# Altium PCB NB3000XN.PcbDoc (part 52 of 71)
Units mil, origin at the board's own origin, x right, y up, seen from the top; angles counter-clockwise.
Board outline 9527.56 x 6929.77 mil, 6 copper layers (Top Layer, GND+SHIELD, MidLayer1, MidLayer2, P2 - 3V3+5V0, Bottom Layer), stack 62.375 mil thick; 832 components, 1027 nets, 4655 pads, 4981 vias.
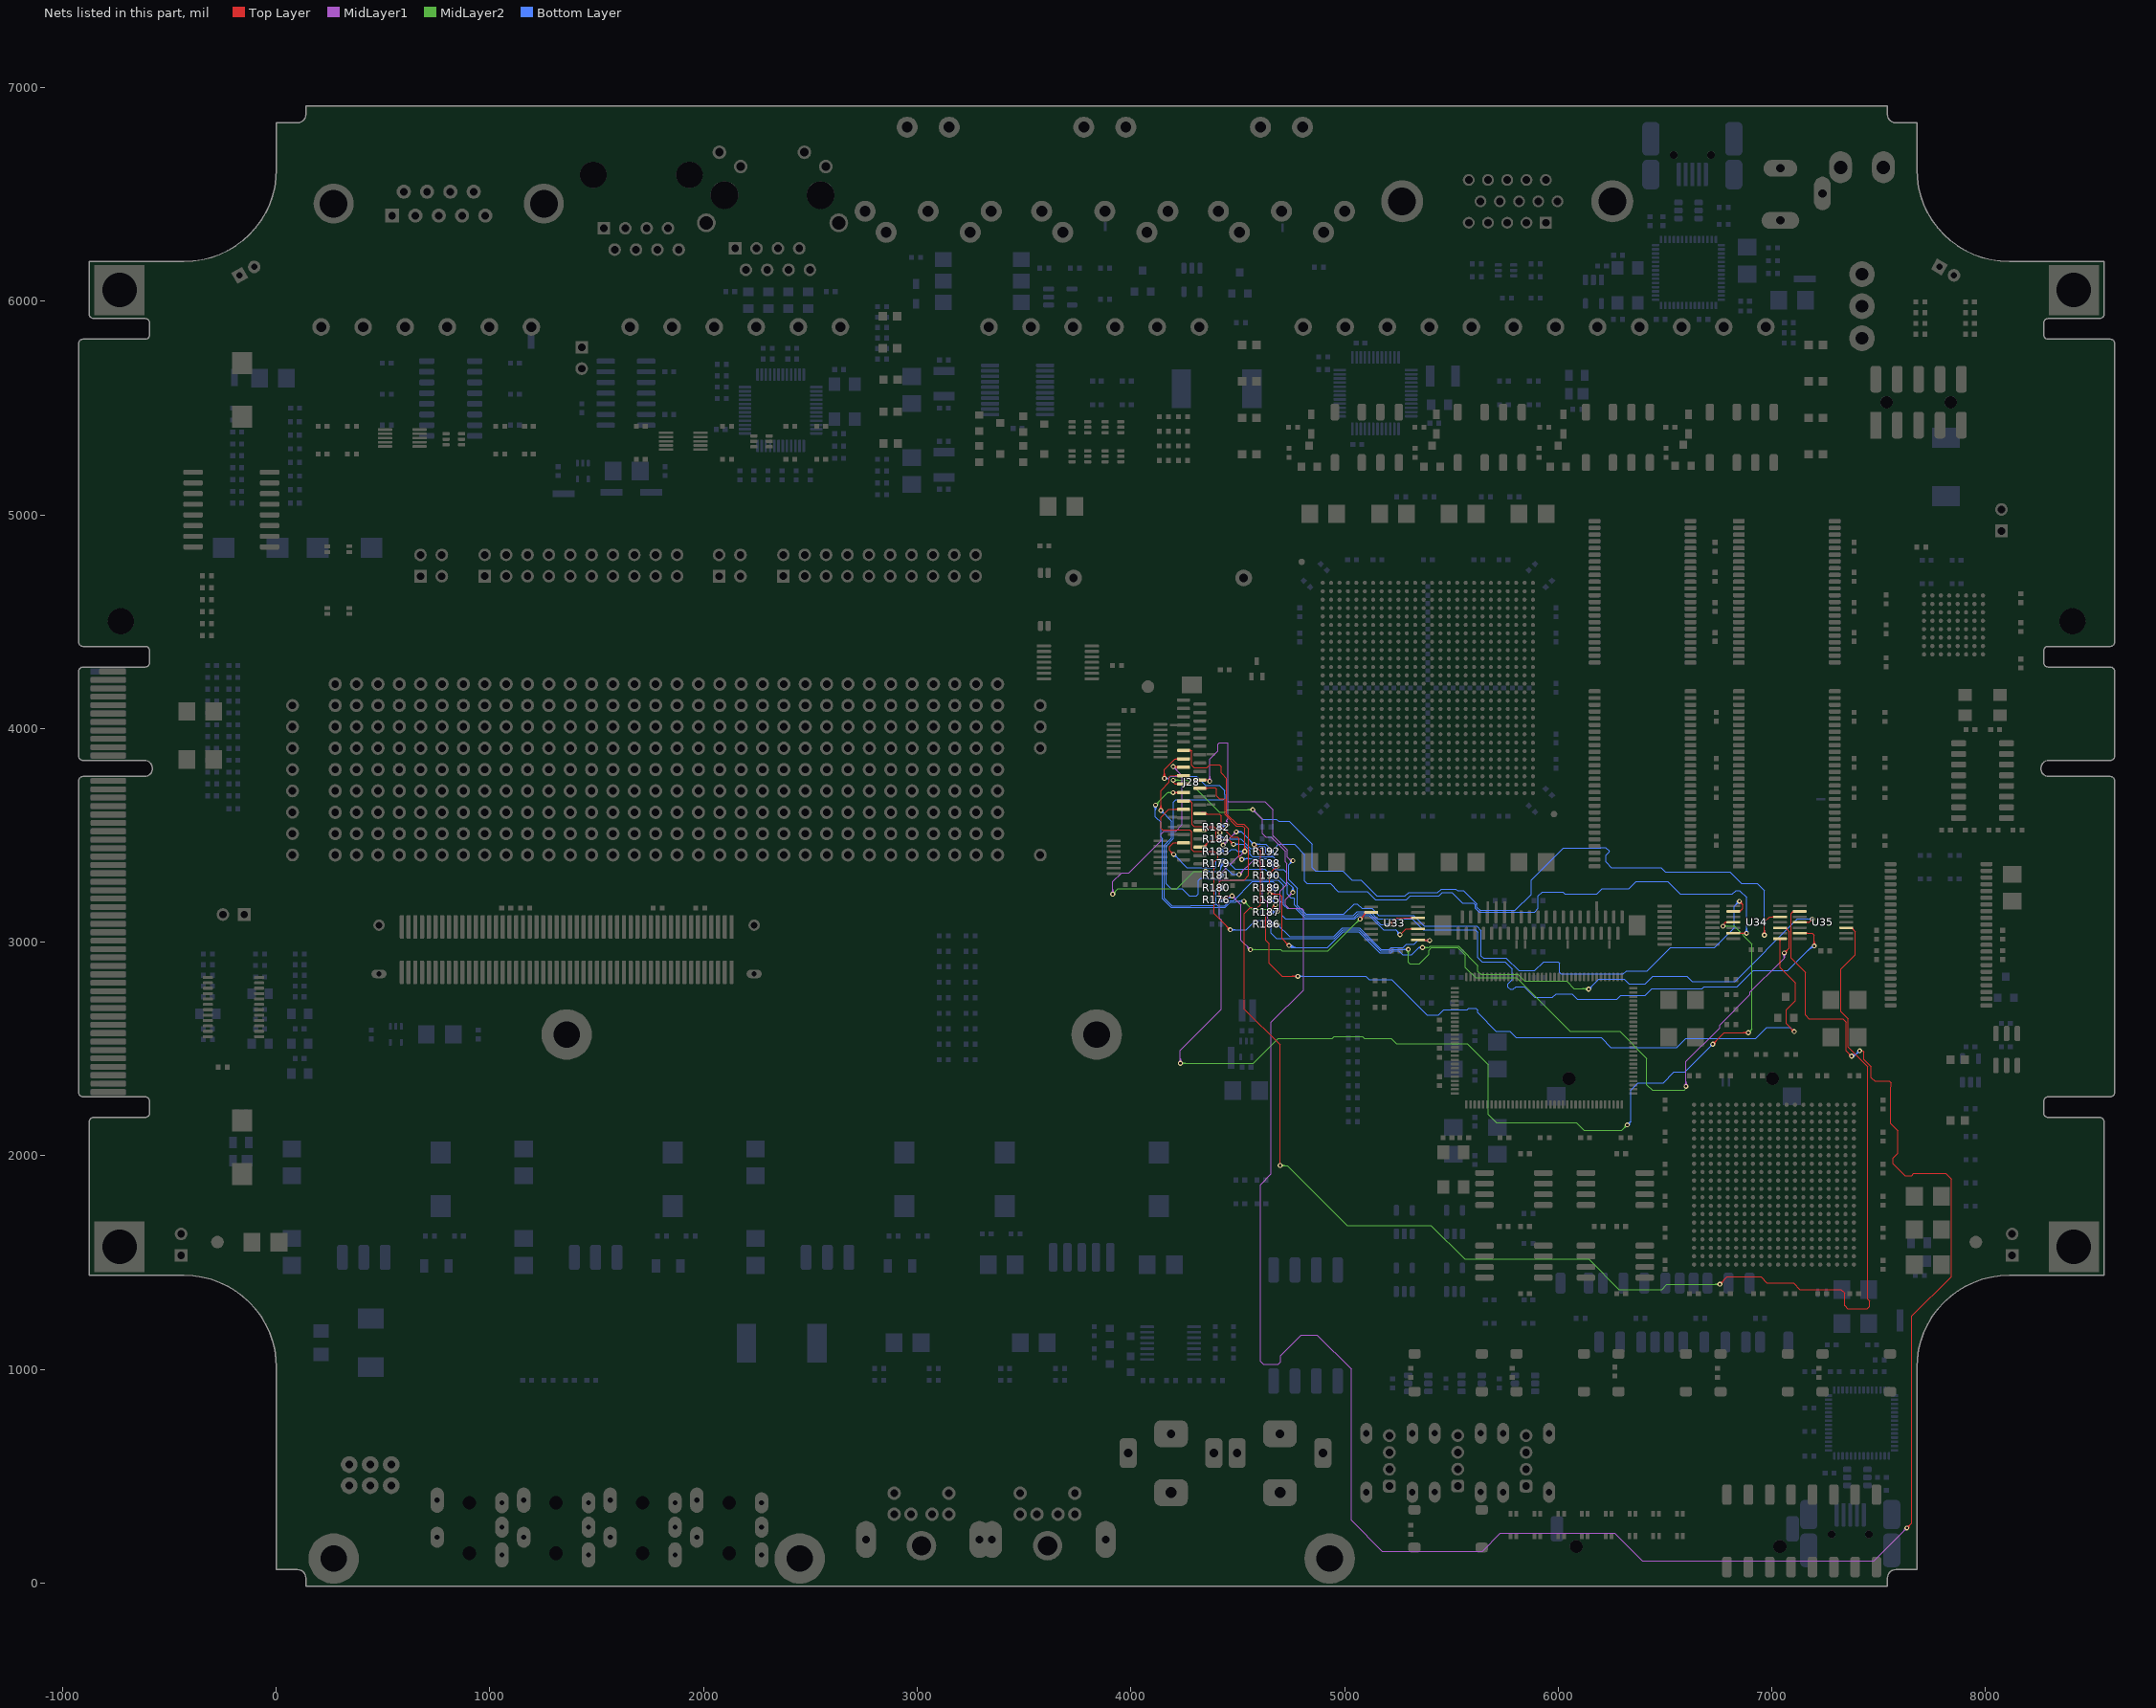
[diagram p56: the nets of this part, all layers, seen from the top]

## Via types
v1: diameter 23, hole 11.81, Top Layer to Bottom Layer, 3672 vias
v2: diameter 26, hole 11.81, Top Layer to Bottom Layer, 461 vias
v3: diameter 19, hole 11.81, Top Layer to Bottom Layer, tented both sides, 396 vias
v4: diameter 23.62, hole 11.81, Top Layer to Bottom Layer, 288 vias
v5: diameter 20, hole 11.81, Top Layer to Bottom Layer, 91 vias
v6: diameter 23, hole 11.81, Top Layer to Bottom Layer, tented both sides, 50 vias
v7: diameter 31, hole 11.81, Top Layer to Bottom Layer, 15 vias
v8: diameter 27.56, hole 11.81, Top Layer to Bottom Layer, tented both sides, 4 vias
v9: diameter 29, hole 11.81, Top Layer to Bottom Layer, 3 vias
v10: diameter 21, hole 11.81, Top Layer to Bottom Layer, 1 vias

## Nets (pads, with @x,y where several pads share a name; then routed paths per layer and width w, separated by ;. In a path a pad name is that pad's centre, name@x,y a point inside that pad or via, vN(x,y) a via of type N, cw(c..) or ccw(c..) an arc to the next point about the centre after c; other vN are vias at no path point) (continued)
LEDS#.LED2.RED: J28.13 R176.2 U33.2 | length 2543.8
  Top Layer w4: J28.13@4246.61,3897.64 4281.86,3897.64 ; J28.13@4273.12,3893.73 cw(c4281.86,3885.93) 4281.86,3897.64 ; J28.13@4273.12,3901.55 ccw(c4281.86,3909.34) 4281.86,3897.64 ; 4451.86,3210 4458.56,3216.71 ; v1(4473.52,3216.71) 4458.56,3216.71 ; v1(5073.52,3108.37) 5098.52,3133.37 ; v1@5073.52,3113.87 ccw(c5073.52,3127.15) 5082.91,3117.76 ccw(c5092.3,3108.37) v1@5079.02,3108.37 ; v1@5073.52,3117.87 ccw(c5073.52,3140.81) 5089.74,3124.59 ccw(c5105.96,3108.37) v1@5083.02,3108.37 ; 5087.42,3122.27 ccw(c5070.28,3139.41) U33.2@5094.52,3139.41 ; 5094.25,3129.1 ccw(c5083.94,3139.41) U33.2@5098.52,3139.41 ; U33.2@5096.97,3135.72 cw(c5095.97,3133.38) 5098.52,3133.38 ; U33.2@5100.08,3135.73 ccw(c5101.08,3133.38) 5098.52,3133.38 ; U33.2@5125,3139.41 U33.2@5098.52,3139.41 ; 4281.86,3897.64 4283.52,3895.97 4283.52,3828.71 4295.52,3816.71 4356.71,3816.71 4370.58,3830.58 4415,3830.58 4423.52,3822.06 4423.52,3791.71 4448.52,3766.71 4448.52,3606.71 4448.52,3601 4496.82,3552.71 4529.19,3552.71 4551.19,3530.71 4551.19,3312.9 4530,3291.71 4425.19,3291.71 4415.19,3281.71 4415.19,3216.71 4423.52,3208.37 4450.23,3208.37 4458.56,3216.71 ; 5098.52,3133.37 U33.2@5098.52,3139.41
  MidLayer1 w4: v1@4473.52,3207.21 cw(c4473.52,3184.27) 4489.74,3200.49 cw(c4505.96,3216.71) v1@4483.02,3216.71 ; v1@4473.52,3211.21 cw(c4473.52,3197.93) 4482.91,3207.32 cw(c4492.3,3216.71) v1@4479.02,3216.71 ; v1(4473.52,3216.71) 4515.19,3175.04 4515.19,3009.37 v1(4559.52,2965.04) ; v1@4550.02,2965.04 ccw(c4527.09,2965.04) 4543.31,2981.26 ccw(c4559.52,2997.48) v1@4559.52,2974.54 ; v1@4554.02,2965.04 ccw(c4540.75,2965.04) 4550.14,2974.43 ccw(c4559.52,2983.82) v1@4559.52,2970.54
  MidLayer2 w4: v1(4559.52,2965.04) 4700.19,2965.04 4706.86,2958.37 4923.52,2958.37 v1(5073.52,3108.37) ; v1@4563.41,2961.15 cw(c4572.8,2951.76) 4572.8,2965.04 cw(c4572.8,2978.32) v1@4563.41,2968.93 ; v1@4566.24,2958.32 cw(c4582.46,2942.11) 4582.46,2965.04 cw(c4582.46,2987.98) v1@4566.24,2971.76 ; v1@5064.02,3108.37 cw(c5041.09,3108.37) 5057.31,3092.16 cw(c5073.52,3075.94) v1@5073.52,3098.87 ; v1@5068.02,3108.37 cw(c5054.75,3108.37) 5064.14,3098.99 cw(c5073.52,3089.6) v1@5073.52,3102.87
  Bottom Layer w4: R176.2@4421.18,3198.75 4440.86,3198.75 ; R176.2@4428.39,3192.85 cw(c4440.86,3182.64) 4440.86,3198.75 ; R176.2@4428.39,3204.65 ccw(c4440.86,3214.86) 4440.86,3198.75 ; 4455.42,3208.37 ccw(c4455.42,3221.63) v1@4468.22,3218.15 ; 4460.66,3208.37 ccw(c4460.66,3220.21) v1@4472.08,3217.1 ; v1@4464.36,3219.2 cw(c4450.19,3223.06) 4450.19,3208.37 ; v1(4473.52,3216.71) 4465.19,3208.37 4450.19,3208.37 ; 4440.86,3198.75 4440.86,3199.04 4450.19,3208.37
LEDS#.LED3.BLUE: J28.19 R180.2 U33.10 | length 2457.1
  Top Layer w4: v1@4133.47,3623.43 ccw(c4117.26,3639.64) 4140.19,3639.64 ccw(c4163.13,3639.64) v1@4146.91,3623.43 ; v1@4136.3,3620.6 ccw(c4126.91,3629.99) 4140.19,3629.99 ccw(c4153.47,3629.99) v1@4144.08,3620.6 ; v1(4140.19,3616.71) 4140.19,3710.19 4180,3750 4180,3775 4185,3780 4246.14,3780 J28.19@4246.61,3779.53 ; 4209.17,3780 cw(c4209.17,3764.21) J28.19@4220.33,3775.37 ; 4211.45,3780 ccw(c4211.45,3792.57) J28.19@4220.33,3783.68 ; v1(5260,3035) 5260.15,3035 5287.79,3062.64 U33.10@5343.5,3062.64 ; U33.10@5314.2,3059.81 ccw(c5307.37,3052.98) 5307.37,3062.64 ccw(c5307.37,3072.29) U33.10@5314.2,3065.47
  Bottom Layer w4: v1@4140.19,3607.21 cw(c4140.19,3584.27) 4156.41,3600.49 cw(c4172.63,3616.71) v1@4149.69,3616.71 ; v1@4140.19,3611.21 cw(c4140.19,3597.93) 4149.58,3607.32 cw(c4158.97,3616.71) v1@4145.69,3616.71 ; v1(4140.19,3616.71) 4190.19,3566.71 4190.19,3487.37 4156.86,3454.04 4156.86,3235 4156.86,3206 4191.82,3171.04 4281.04,3171.04 4281.37,3171.37 4390.19,3171.37 4398.52,3179.71 ; R180.2@4412.74,3251.67 ccw(c4406.52,3248.76) 4406.52,3255.62 ; R180.2@4412.74,3259.58 cw(c4406.52,3262.49) 4406.52,3255.62 ; R180.2@4421.18,3255.62 4406.52,3255.62 ; 5241.26,3057.3 cw(c5218.96,3035) v1@5250.5,3035 ; 5248.09,3050.47 cw(c5232.62,3035) v1@5254.5,3035 ; 5249.87,3048.7 ccw(c5260,3058.83) v1@5260,3044.5 ; v1(5260,3035) 5260.15,3035.15 5260.15,3038.42 5240.19,3058.37 5182.86,3058.37 5115.19,3126.04 5066.19,3126.04 5048.52,3108.37 4723.52,3108.37 4706.86,3125.04 4706.86,3183.37 4673.52,3216.71 4673.52,3275.04 4665.19,3283.37 4569.86,3283.37 4481.86,3195.37 4462.9,3195.37 4438.56,3171.04 4407.19,3171.04 4403.19,3175.04 4398.52,3179.71 ; 4398.52,3179.71 4398.52,3247.62 4406.52,3255.62
LEDS#.LED3.GREEN: J28.15 R181.2 U33.12 | length 2846.8
  Top Layer w4: v1@4150.14,3773.43 ccw(c4133.92,3789.64) 4156.86,3789.64 ccw(c4179.79,3789.64) v1@4163.57,3773.43 ; v1@4152.97,3770.6 ccw(c4143.58,3779.99) 4156.86,3779.99 ccw(c4170.14,3779.99) v1@4160.75,3770.6 ; v1(4156.86,3766.71) 4156.86,3808.37 4206.75,3858.27 J28.15@4246.61,3858.27 J28.15@4248.52,3858.27 ; J28.15@4220.33,3854.11 ccw(c4210.31,3844.09) 4210.31,3858.27 ccw(c4210.31,3872.45) J28.15@4220.33,3862.42 ; v1(5215.19,3083.37) 5245.64,3113.82 U33.12@5343.5,3113.82 ; v1@5215.19,3088.87 ccw(c5215.19,3102.15) 5224.58,3092.76 ccw(c5233.97,3083.37) v1@5220.69,3083.37 ; v1@5215.19,3092.87 ccw(c5215.19,3115.81) 5231.41,3099.59 ccw(c5247.63,3083.37) v1@5224.69,3083.37 ; U33.12@5314.2,3110.99 ccw(c5307.37,3104.16) 5307.37,3113.82 ccw(c5307.37,3123.48) U33.12@5314.2,3116.65
  Bottom Layer w4: v1(4156.86,3766.71) 4175.67,3766.71 ; v1@4164.5,3761.07 cw(c4175.67,3752.84) 4175.67,3766.71 ; v1@4164.5,3772.35 ccw(c4175.67,3780.58) 4175.67,3766.71 ; R181.2@4421.18,3312.5 4421.18,3299.71 4415.85,3294.37 ; 4440,3692.63 4440,3708.69 4415.31,3733.37 4348.52,3733.37 4305.86,3776.04 4185,3776.04 4175.67,3766.71 ; 4440.19,3692.63 4440.19,3674.04 4432.86,3666.71 4211.71,3666.71 4200,3655 4200,3485.87 4164.86,3450.73 4164.86,3272.39 4187.21,3250.04 4240.19,3250.04 4273.52,3216.71 4306.86,3216.71 4315.19,3225.04 4315.19,3287.71 4327.52,3300.04 4357.86,3300.04 4363.52,3294.37 4415.85,3294.37 ; v1@5208.47,3076.66 ccw(c5192.26,3060.44) 5192.26,3083.37 ccw(c5192.26,3106.31) v1@5208.47,3090.09 ; v1@5211.3,3079.49 ccw(c5201.91,3070.1) 5201.91,3083.37 ccw(c5201.91,3096.65) v1@5211.3,3087.26 ; v1(5215.19,3083.37) 5169.17,3083.37 5118.5,3134.04 5062.88,3134.04 5045.21,3116.37 4812.54,3116.37 4770.54,3158.37 4731.86,3158.37 4715.19,3175.04 4715.19,3266.71 4690.19,3291.71 4418.51,3291.71 4415.85,3294.37
LEDS#.LED3.RED: J28.17 R179.2 U33.8 | length 3712.4
  Top Layer w4: v1(4198.19,3822.04) 4201.86,3818.37 v1@4205.19,3818.37 ; v1@4199.25,3823.1 ccw(c4209.4,3833.25) 4209.4,3818.9 ; v1@4202.08,3825.93 ccw(c4219.06,3842.91) J28.17@4219.06,3818.9 ; v1@4204.91,3815.32 cw(c4213.54,3806.69) 4213.54,3818.9 ; v1@4204.91,3828.76 ccw(c4228.71,3852.56) J28.17@4228.71,3818.9 ; v1@4205.71,3818.9 J28.17@4246.61,3818.9 ; J28.17@4220.33,3814.74 ccw(c4210.31,3804.72) 4210.31,3818.9 ccw(c4210.31,3833.08) J28.17@4220.33,3823.05 ; U33.8@5343.5,3011.46 5340.19,3011.46 5340.19,3008.37 5343.5,3008.37 v1(5398.52,3008.37) ; U33.8@5369.98,3011.46 ccw(c5377.43,3018.9) 5377.43,3008.37 ; U33.8@5372.81,3014.29 ccw(c5387.08,3028.56) v1@5387.08,3008.37 ; v1@5391.81,3001.66 ccw(c5375.59,2985.44) 5375.59,3008.37 ccw(c5375.59,3031.31) v1@5391.81,3015.09 ; v1@5394.64,3004.49 ccw(c5385.25,2995.1) 5385.25,3008.37 ccw(c5385.25,3021.65) v1@5394.64,3012.26
  MidLayer1 w4: v1@3908.47,3231.76 ccw(c3892.26,3247.98) 3915.19,3247.98 ccw(c3938.13,3247.98) v1@3921.91,3231.76 ; v1@3911.3,3228.93 ccw(c3901.91,3238.32) 3915.19,3238.32 ccw(c3928.47,3238.32) v1@3919.08,3228.93 ; v1(3915.19,3225.04) 3915.19,3283.37 3956.86,3325.04 3991.19,3325.04 4140.19,3474.04 4140.19,3505.04 4155.15,3520 4210.15,3520 4240.19,3550.04 4240.19,3780.04 v1(4198.19,3822.04) ; v1@4198.19,3812.54 cw(c4198.19,3789.61) 4214.41,3805.82 cw(c4230.63,3822.04) v1@4207.69,3822.04 ; v1@4198.19,3816.54 cw(c4198.19,3803.26) 4207.58,3812.65 cw(c4216.97,3822.04) v1@4203.69,3822.04 ; v1(4506.86,3316.71) 4573.52,3383.37 4598.52,3383.37 4615.19,3366.71 4615.19,3208.37 4640.19,3183.37 4640.19,3108.37 4665.19,3083.37 ; v1@4506.86,3322.21 ccw(c4506.86,3335.49) 4516.25,3326.1 ccw(c4525.64,3316.71) v1@4512.36,3316.71 ; v1@4506.86,3326.21 ccw(c4506.86,3349.14) 4523.07,3332.93 ccw(c4539.29,3316.71) v1@4516.36,3316.71 ; v1@4678.24,3077.28 ccw(c4665.19,3066.37) 4665.19,3083.37 ; v1@4678.24,3089.47 cw(c4665.19,3100.38) 4665.19,3083.37 ; v1@4681.31,3079.85 ccw(c4673.75,3073.53) 4673.75,3083.37 ccw(c4673.75,3093.22) v1@4681.31,3086.9 ; v1(4685.52,3083.37) 4665.19,3083.37
  MidLayer2 w4: v1(3915.19,3225.04) 3940.52,3250.37 4214.19,3250.37 4295.19,3331.37 v1(4349.52,3331.37) ; v1@3915.19,3230.54 ccw(c3915.19,3243.82) 3924.58,3234.43 ccw(c3933.97,3225.04) v1@3920.69,3225.04 ; v1@3915.19,3234.54 ccw(c3915.19,3257.48) 3931.41,3241.26 ccw(c3947.63,3225.04) v1@3924.69,3225.04 ; v1@4342.81,3324.66 ccw(c4326.59,3308.44) 4326.59,3331.37 ccw(c4326.59,3354.31) v1@4342.81,3338.09 ; v1@4345.64,3327.49 ccw(c4336.25,3318.1) 4336.25,3331.37 ccw(c4336.25,3344.65) v1@4345.64,3335.26
  Bottom Layer w4: v1(4349.52,3331.37) 4411.37,3331.37 4421.18,3341.18 R179.2@4421.18,3369.38 ; v1@4353.41,3327.49 cw(c4362.8,3318.1) 4362.8,3331.37 cw(c4362.8,3344.65) v1@4353.41,3335.26 ; v1@4356.24,3324.66 cw(c4372.46,3308.44) 4372.46,3331.37 cw(c4372.46,3354.31) v1@4356.24,3338.09 ; R179.2@4414.59,3362.29 cw(c4398.68,3346.39) 4421.18,3346.39 cw(c4443.68,3346.39) R179.2@4427.77,3362.29 ; R179.2@4417.42,3365.12 cw(c4408.34,3356.04) 4421.18,3356.04 cw(c4434.02,3356.04) R179.2@4424.94,3365.12 ; R179.2@4421.18,3359.56 cw(c4421.18,3335.88) 4437.93,3352.63 ; R179.2@4421.18,3363.56 cw(c4421.18,3349.54) R179.2@4431.1,3359.46 ; R179.2@4426.5,3368.88 ccw(c4438.15,3368.88) R179.2@4429.91,3360.64 ; R179.2@4429.85,3360.7 4473.85,3316.71 v1(4506.86,3316.71) ; R179.2@4430.5,3368.88 ccw(c4451.81,3368.88) 4436.74,3353.81 ; v1@4500.14,3309.99 ccw(c4483.92,3293.77) 4483.92,3316.71 ccw(c4483.92,3339.64) v1@4500.14,3323.43 ; v1@4502.97,3312.82 ccw(c4493.58,3303.43) 4493.58,3316.71 ccw(c4493.58,3329.99) v1@4502.97,3320.6 ; v1@4685.52,3073.87 cw(c4685.52,3050.94) 4701.74,3067.16 cw(c4717.96,3083.37) v1@4695.02,3083.37 ; v1@4685.52,3077.87 cw(c4685.52,3064.6) 4694.91,3073.99 cw(c4704.3,3083.37) v1@4691.02,3083.37 ; v1(4685.52,3083.37) 4743.19,3025.71 4948.52,3025.71 4989.52,3066.71 5071.15,3066.71 5171.48,2966.37 5210.93,2966.37 5219.37,2974.81 5273.29,2974.81 5290.19,2991.71 5326.5,2991.71 5343.17,3008.37 v1(5398.52,3008.37) ; v1@5391.81,3001.66 ccw(c5375.59,2985.44) 5375.59,3008.37 ccw(c5375.59,3031.31) v1@5391.81,3015.09 ; v1@5394.64,3004.49 ccw(c5385.25,2995.1) 5385.25,3008.37 ccw(c5385.25,3021.65) v1@5394.64,3012.26
LEDS#.LED4.BLUE: J28.22 R183.2 U34.4 | length 6447.5
  Top Layer w4: J28.22@4323.39,3720.47 4361.39,3720.47 4364.79,3723.88 4395,3723.88 4401.5,3717.38 4401.5,3695 ; J28.22@4349.67,3716.32 cw(c4359.69,3706.29) 4359.69,3720.47 cw(c4359.69,3734.66) J28.22@4349.67,3724.63 ; 4401.5,3705 4401.5,3695 ; v1@4526.47,3431.76 ccw(c4510.26,3447.98) 4533.19,3447.98 ccw(c4556.13,3447.98) v1@4539.91,3431.76 ; v1@4529.3,3428.93 ccw(c4519.91,3438.32) 4533.19,3438.32 ccw(c4546.47,3438.32) v1@4537.08,3428.93 ; v1(4533.19,3425.04) 4533.19,3534.37 4522.86,3544.71 4493.5,3544.71 4440.19,3598.02 4440.19,3666.81 4435,3672 4415,3672 4401.5,3685.5 4401.5,3695 ; v1(6723.86,2523.04) 6777.52,2576.71 v1(6890.19,2576.71) ; v1@6723.86,2528.54 ccw(c6723.86,2541.82) 6733.25,2532.43 ccw(c6742.64,2523.04) v1@6729.36,2523.04 ; v1@6723.86,2532.54 ccw(c6723.86,2555.48) 6740.07,2539.26 ccw(c6756.29,2523.04) v1@6733.36,2523.04 ; v1(6771.52,3075.04) 6779.52,3083.04 6779.52,3090.89 6781.85,3093.23 U34.4@6820,3093.23 ; U34.4@6790.69,3090.4 ccw(c6783.86,3083.57) 6783.86,3093.23 ccw(c6783.86,3102.89) U34.4@6790.69,3096.06 ; v1@6883.47,2569.99 ccw(c6867.26,2553.77) 6867.26,2576.71 ccw(c6867.26,2599.64) v1@6883.47,2583.43 ; v1@6886.3,2572.82 ccw(c6876.91,2563.43) 6876.91,2576.71 ccw(c6876.91,2589.99) v1@6886.3,2580.6
  MidLayer1 w4: v1@4225.14,2440.09 ccw(c4208.92,2456.31) 4231.86,2456.31 ccw(c4254.79,2456.31) v1@4238.57,2440.09 ; v1@4227.97,2437.26 ccw(c4218.58,2446.65) 4231.86,2446.65 ccw(c4245.14,2446.65) v1@4235.75,2437.26 ; v1(4231.86,2433.37) 4231.86,2494.08 4423.52,2685.75 4423.52,3104.1 4415.19,3112.44 4415.19,3315.04 4505.15,3405 ; 4505,3405 4505.15,3405 ; v1@4523.69,3425.04 cw(c4500.76,3425.04) 4516.97,3408.82 cw(c4533.19,3392.61) v1@4533.19,3415.54 ; v1@4527.69,3425.04 cw(c4514.41,3425.04) 4523.8,3415.65 cw(c4533.19,3406.26) v1@4533.19,3419.54 ; v1(4533.19,3425.04) 4513.15,3405 4505.15,3405
  MidLayer2 w4: v1(4231.86,2433.37) 4573.52,2433.37 4689.52,2549.37 4943.31,2549.37 4951.94,2558 5083.55,2558 5092.05,2549.5 5218.19,2549.5 5242.65,2525.04 5574.52,2525.04 5673.52,2426.04 5673.52,2192.79 5711.94,2154.37 6085.86,2154.37 6120.23,2120 6298.82,2120 v1(6323.52,2144.71) ; v1@4235.75,2429.49 cw(c4245.14,2420.1) 4245.14,2433.37 cw(c4245.14,2446.65) v1@4235.75,2437.26 ; v1@4238.57,2426.66 cw(c4254.79,2410.44) 4254.79,2433.37 cw(c4254.79,2456.31) v1@4238.57,2440.09 ; v1@6314.02,2144.71 cw(c6291.09,2144.71) 6307.31,2128.49 cw(c6323.52,2112.27) v1@6323.52,2135.21 ; v1@6318.02,2144.71 cw(c6304.75,2144.71) 6314.14,2135.32 cw(c6323.52,2125.93) v1@6323.52,2139.21 ; v1(6771.52,3075.04) 6823.52,3075.04 6906.86,2991.71 6906.86,2593.37 v1(6890.19,2576.71) ; v1@6775.41,3071.15 cw(c6784.8,3061.76) 6784.8,3075.04 cw(c6784.8,3088.32) v1@6775.41,3078.93 ; v1@6778.24,3068.32 cw(c6794.46,3052.11) 6794.46,3075.04 cw(c6794.46,3097.98) v1@6778.24,3081.76 ; v1@6890.19,2582.21 ccw(c6890.19,2595.49) 6899.58,2586.1 ccw(c6908.97,2576.71) v1@6895.69,2576.71 ; v1@6890.19,2586.21 ccw(c6890.19,2609.14) 6906.41,2592.93 ccw(c6922.63,2576.71) v1@6899.69,2576.71
  Bottom Layer w4: R183.2@4421.18,3426.25 4461.25,3426.25 4470,3435 4490,3435 4499.96,3425.04 v1(4533.19,3425.04) ; R183.2@4424.94,3422.49 cw(c4434.02,3413.41) 4434.02,3426.25 cw(c4434.02,3439.09) R183.2@4424.94,3430.01 ; R183.2@4427.77,3419.66 cw(c4443.68,3403.75) 4443.68,3426.25 cw(c4443.68,3448.75) R183.2@4427.77,3432.84 ; v1@4526.47,3418.32 ccw(c4510.26,3402.11) 4510.26,3425.04 ccw(c4510.26,3447.98) v1@4526.47,3431.76 ; v1@4529.3,3421.15 ccw(c4519.91,3411.76) 4519.91,3425.04 ccw(c4519.91,3438.32) v1@4529.3,3428.93 ; v1(6323.52,2144.71) 6340.19,2161.37 6340.19,2308.88 6373.35,2342.04 6492.9,2342.04 6542.9,2392.04 6592.86,2392.04 v1(6723.86,2523.04) ; v1@6323.52,2150.21 ccw(c6323.52,2163.49) 6332.91,2154.1 ccw(c6342.3,2144.71) v1@6329.02,2144.71 ; v1@6323.52,2154.21 ccw(c6323.52,2177.14) 6339.74,2160.93 ccw(c6355.96,2144.71) v1@6333.02,2144.71 ; v1@6714.36,2523.04 cw(c6691.42,2523.04) 6707.64,2506.82 cw(c6723.86,2490.61) v1@6723.86,2513.54 ; v1@6718.36,2523.04 cw(c6705.08,2523.04) 6714.47,2513.65 cw(c6723.86,2504.26) v1@6723.86,2517.54
LEDS#.LED4.GREEN: J28.25 R184.2 U34.6 | length 3853.9
  Top Layer w4: J28.25@4246.61,3661.42 4277.34,3661.42 ; J28.25@4268.58,3663.54 cw(c4269.58,3650.05) 4279.14,3659.61 ; J28.25@4268.88,3659.55 cw(c4270.43,3638.55) 4285.31,3653.44 ; J28.25@4270.04,3660.07 cw(c4274.36,3655.6) 4278.76,3660 ; J28.25@4272.82,3657.19 cw(c4277.19,3652.67) 4281.63,3657.12 ; J28.25@4274.21,3659.28 cw(c4277.34,3658.06) 4277.34,3661.42 ; J28.25@4274.21,3663.55 ccw(c4277.34,3664.77) 4277.34,3661.42 ; v1(4416.52,3512.04) 4386.86,3541.71 4295.52,3541.71 4287.19,3550.04 4287.19,3651.56 4277.34,3661.42 ; U34.6@6820,3042.05 6823.52,3042.05 6823.52,3041.71 v1(6881.86,3041.71) ; U34.6@6849.31,3039.22 cw(c6855.32,3033.21) 6855.32,3041.71 ; U34.6@6849.31,3044.88 ccw(c6856.96,3052.53) 6856.96,3041.71 ; v1@6875.14,3034.99 ccw(c6858.92,3018.77) 6858.92,3041.71 ccw(c6858.92,3064.64) v1@6875.14,3048.43 ; v1@6877.97,3037.82 ccw(c6868.58,3028.43) 6868.58,3041.71 ccw(c6868.58,3054.99) v1@6877.97,3045.6
  Bottom Layer w4: v1@4410.62,3504.6 cw(c4393.31,3482.75) R184.2@4421.18,3482.75 ; v1@4413.11,3507.73 cw(c4399.87,3491.03) R184.2@4421.18,3491.03 ; R184.2@4414.59,3490.21 ccw(c4398.68,3506.12) 4421.18,3506.12 ccw(c4443.68,3506.11) R184.2@4427.77,3490.21 ; v1@4415.59,3510.87 cw(c4406.43,3499.3) 4421.18,3499.3 ; v1(4416.52,3512.04) 4421.18,3507.38 R184.2@4421.18,3483.12 4421.26,3483.04 4515.52,3483.04 4559.86,3438.71 4594.19,3438.71 4605.52,3450.04 4623.52,3450.04 4631.86,3441.71 4631.86,3416.71 4640.19,3408.37 4671.86,3408.37 4673.52,3410.04 4680,3416.52 4680,3448.18 4690.19,3458.37 4765.19,3458.37 4813.52,3410.04 4813.52,3286.48 4824.96,3275.04 4932.86,3275.04 4970.52,3237.37 5107.19,3237.37 5144.52,3200.04 5290.19,3200.04 5306.86,3216.71 5442.52,3216.71 5458.86,3233.04 5502.86,3233.04 5552.52,3183.37 5603.88,3183.37 5612.21,3175.04 5612.21,3159.69 5613.52,3158.37 5630.86,3141.04 5889.52,3141.04 5906.86,3158.37 5906.86,3216.71 5925.15,3235 6021.9,3235 6031.86,3225.04 6181.86,3225.04 6206.86,3250.04 6331.86,3250.04 6365.19,3283.37 6513.31,3283.37 6571.65,3225.04 6815.19,3225.04 6832.86,3242.71 6848.52,3242.71 6881.86,3209.37 v1(6881.86,3041.71) ; R184.2@4417.42,3487.38 ccw(c4408.34,3496.46) 4421.18,3496.46 ccw(c4434.02,3496.46) R184.2@4424.94,3487.38 ; 4421.18,3500.35 cw(c4428.22,3500.35) v1@4423.24,3505.32 ; R184.2@4424.94,3479.36 cw(c4433.82,3470.49) 4433.82,3483.04 ; R184.2@4424.94,3486.89 ccw(c4434.23,3496.17) 4434.23,3483.04 ; R184.2@4427.77,3476.54 cw(c4443.48,3460.83) 4443.48,3483.04 ; R184.2@4427.77,3489.71 ccw(c4443.88,3505.83) 4443.88,3483.04 ; v1@6875.14,3048.43 ccw(c6858.92,3064.64) 6881.86,3064.64 ccw(c6904.79,3064.64) v1@6888.57,3048.43 ; v1@6877.97,3045.6 ccw(c6868.58,3054.99) 6881.86,3054.99 ccw(c6895.14,3054.99) v1@6885.75,3045.6
LEDS#.LED4.RED: J28.20 R182.2 U34.2 | length 4544
  Top Layer w4: J28.20@4323.39,3759.84 4355.52,3759.84 ; J28.20@4350.64,3756.98 cw(c4355.52,3754.25) 4355.52,3759.84 ; J28.20@4350.64,3762.71 ccw(c4355.52,3765.44) 4355.52,3759.84 ; v1(4369.19,3753.04) 4360.86,3761.37 4357.06,3761.37 4355.52,3759.84 ; U34.2@6820,3144.41 6823.52,3144.41 6823.52,3141.71 6848.52,3141.71 6865.19,3158.37 6865.19,3174.37 v1(6847.86,3191.71) ; U34.2@6846.48,3144.41 ccw(c6846.48,3155.87) 6854.58,3147.77 ; U34.2@6846.48,3148.41 ccw(c6846.48,3169.52) 6861.41,3154.59 ; v1@6847.86,3182.21 cw(c6847.86,3159.27) 6864.07,3175.49 cw(c6880.29,3191.71) v1@6857.36,3191.71 ; v1@6847.86,3186.21 cw(c6847.86,3172.93) 6857.25,3182.32 cw(c6866.64,3191.71) v1@6853.36,3191.71
  MidLayer1 w4: v1@4362.47,3759.76 ccw(c4346.26,3775.98) 4369.19,3775.98 ccw(c4392.13,3775.98) v1@4375.91,3759.76 ; v1@4365.3,3756.93 ccw(c4355.91,3766.32) 4369.19,3766.32 ccw(c4382.47,3766.32) v1@4373.08,3756.93 ; v1(4369.19,3753.04) 4369.19,3856.75 4406.86,3894.41 4406.86,3926.04 4415.19,3934.37 4453.52,3934.37 4454.52,3933.37 4454.52,3660 ; v1@4442.42,3557.32 ccw(c4431.47,3570.39) 4448.52,3570.39 ; v1@4444.99,3554.26 ccw(c4438.65,3561.82) 4448.52,3561.82 ccw(c4458.4,3561.82) v1@4452.06,3554.26 ; v1(4448.52,3550.04) 4448.52,3570.39 ; v1@4454.63,3557.32 cw(c4465.58,3570.39) 4448.52,3570.39 ; 4736.86,3393.04 ccw(c4747.85,3404.03) v1@4754.48,3389.97 ; 4740.88,3389.02 ccw(c4750.43,3398.56) v1@4756.18,3386.35 ; 4744.9,3384.99 ccw(c4753,3393.09) v1@4757.88,3382.73 ; v1(4758.52,3381.37) 4748.52,3381.37 4731.86,3398.04 4731.86,3432.37 4665.19,3499.04 4665.19,3619.37 4626.19,3658.37 4456.15,3658.37 4454.52,3660 ; 4448.52,3570.39 4454.52,3576.39 4454.52,3660
  Bottom Layer w4: R182.2@4419.71,3538.25 ccw(c4425.57,3547.16) 4433.1,3539.62 ; R182.2@4421.18,3540 4433.48,3540 v1@4443.52,3550.04 ; R182.2@4421.91,3541.59 ccw(c4428.32,3551.35) 4436.58,3543.09 ; R182.2@4424.1,3544.94 ccw(c4431.08,3555.54) v1@4440.05,3546.57 ; R182.2@4426.3,3548.28 ccw(c4433.83,3559.73) v1@4443.52,3550.04 ; v1(4448.52,3550.04) v1@4443.52,3550.04 ; v1@4749.02,3381.37 cw(c4726.09,3381.37) 4742.31,3365.16 cw(c4758.52,3348.94) v1@4758.52,3371.87 ; v1@4753.02,3381.37 cw(c4739.75,3381.37) 4749.14,3371.99 cw(c4758.52,3362.6) v1@4758.52,3375.87 ; v1(4758.52,3381.37) 4739.19,3362.04 4739.19,3292.71 4779.86,3252.04 4779.86,3171.69 4819.17,3132.37 4997.52,3132.37 5045.15,3180 5059.23,3180 5081.19,3158.04 5128.45,3158.04 5161.11,3125.37 5323.19,3125.37 5373.52,3075.04 5618.17,3075.04 5640.19,3053.02 5640.19,2934.81 ; 5640,2935 5640.19,2934.81 ; v1@6838.36,3191.71 cw(c6815.42,3191.71) 6831.64,3175.49 cw(c6847.86,3159.27) v1@6847.86,3182.21 ; v1@6842.36,3191.71 cw(c6829.08,3191.71) 6838.47,3182.32 cw(c6847.86,3172.93) v1@6847.86,3186.21 ; v1(6847.86,3191.71) 6823.52,3167.37 6823.52,3066.71 6731.86,2975.04 6525.19,2975.04 6416.52,2866.37 6319.86,2866.37 6305.52,2852.04 6013.19,2852.04 6006.86,2858.37 6006.86,2901.04 5999.52,2908.37 5931.67,2908.37 5890,2866.71 5815.19,2866.71 5756.9,2925 5650,2925 5640.19,2934.81
LEDS#.LED5.BLUE: J28.27 R186.2 U34.10 | length 5213.7
  Top Layer w4: J28.27@4220.33,3617.89 ccw(c4210.31,3607.87) 4210.31,3622.05 ccw(c4210.31,3636.23) J28.27@4220.33,3626.2 ; J28.27@4246.61,3622.05 4177.05,3622.05 4140.19,3585.19 4140.19,3532.37 4147.52,3525.04 4276.52,3525.04 4284.86,3516.71 4284.86,3433.37 4293.19,3425.04 4390.19,3425.04 4406.86,3408.37 4406.86,3391.71 4390.19,3375.04 4390.19,3133.37 v1(4465.19,3058.37) ; v1@4455.69,3058.37 ccw(c4432.76,3058.37) 4448.97,3074.59 ccw(c4465.19,3090.81) v1@4465.19,3067.87 ; v1@4459.69,3058.37 ccw(c4446.41,3058.37) 4455.8,3067.76 ccw(c4465.19,3077.15) v1@4465.19,3063.87 ; U34.10@7038.5,3067.64 7040.19,3067.64 7040.19,3066.71 7065.19,3066.71 7081.86,3050.04 7081.86,2973.71 v1(7058.19,2950.04) ; v1@7058.19,2955.54 ccw(c7058.19,2968.82) 7067.58,2959.43 ccw(c7076.97,2950.04) v1@7063.69,2950.04 ; v1@7058.19,2959.54 ccw(c7058.19,2982.48) 7074.41,2966.26 ccw(c7090.63,2950.04) v1@7067.69,2950.04 ; U34.10@7064.98,3063.64 cw(c7064.98,3055.73) 7070.58,3061.32 ; U34.10@7068.98,3067.64 ccw(c7080.39,3067.64) 7072.33,3059.57
  MidLayer1 w4: v1@6591.81,2331.76 ccw(c6575.59,2347.98) 6598.52,2347.98 ccw(c6621.46,2347.98) v1@6605.24,2331.76 ; v1@6594.64,2328.93 ccw(c6585.25,2338.32) 6598.52,2338.32 ccw(c6611.8,2338.32) v1@6602.41,2328.93 ; v1(6598.52,2325.04) 6598.52,2441.71 6755.87,2599.05 6755.87,2612.74 6898.52,2755.39 6898.52,2766.71 7042.94,2911.12 7058.19,2926.37 v1(7058.19,2950.04) ; v1@7051.47,2943.32 cw(c7035.26,2927.11) 7058.19,2927.11 cw(c7081.13,2927.11) v1@7064.91,2943.32 ; v1@7054.3,2946.15 cw(c7044.91,2936.76) 7058.19,2936.76 cw(c7071.47,2936.76) v1@7062.08,2946.15
  MidLayer2 w4: v1@5291.81,2959.99 cw(c5275.59,2943.77) 5298.52,2943.77 cw(c5321.46,2943.77) v1@5305.24,2959.99 ; v1@5294.64,2962.82 cw(c5285.25,2953.43) 5298.52,2953.43 cw(c5311.8,2953.43) v1@5302.41,2962.82 ; v1(5298.52,2966.71) 5298.52,2906.48 5305,2900 5350.34,2900 5394.29,2943.95 5394.29,2962.29 5406,2974 5529.69,2974 5565.19,2938.5 5565.19,2882.04 5613.86,2833.37 5805.25,2833.37 6055.25,2583.37 6288.19,2583.37 6415.19,2456.37 6415.19,2333.37 6440.19,2308.37 6590.86,2308.37 6598.52,2316.04 v1(6598.52,2325.04)
  Bottom Layer w4: v1(4465.19,3058.37) 4540.19,3058.37 4585.49,3103.68 4650.86,3103.68 4656.86,3097.68 4656.86,3041.71 4680.86,3017.71 4951.84,3017.71 4992.51,3058.37 5068.17,3058.37 5168.17,2958.37 5214.25,2958.37 5222.68,2966.81 5255.18,2966.81 5255.29,2966.71 v1(5298.52,2966.71) ; v1@4469.08,3054.49 cw(c4478.47,3045.1) 4478.47,3058.37 cw(c4478.47,3071.65) v1@4469.08,3062.26 ; v1@4471.91,3051.66 cw(c4488.13,3035.44) 4488.13,3058.37 cw(c4488.13,3081.31) v1@4471.91,3065.09 ; R186.2@4649.59,3077.92 cw(c4632.05,3060.38) 4656.86,3060.38 ; 4652.33,3102.2 cw(c4642.4,3092.28) R186.2@4655,3086.07 ; R186.2@4652.42,3080.75 cw(c4641.71,3070.03) 4656.86,3070.03 ; R186.2@4656.18,3085 4656.18,3097.01 4656.85,3097.68 ; 4656.28,3098.25 cw(c4647.69,3089.67) R186.2@4658.59,3084.31 ; 4656.86,3063.64 cw(c4677.05,3063.64) R186.2@4662.77,3077.92 ; v1@5291.81,2959.99 ccw(c5275.59,2943.77) 5275.59,2966.71 ccw(c5275.59,2989.64) v1@5291.81,2973.43 ; v1@5294.64,2962.82 ccw(c5285.25,2953.43) 5285.25,2966.71 ccw(c5285.25,2979.99) v1@5294.64,2970.6
LEDS#.LED5.GREEN: J28.21 R187.2 U34.12 | length 4945.4
  Top Layer w4: v1(4198.52,3758.37) 4198.52,3748.16 4206.52,3740.16 J28.21@4246.61,3740.16 ; J28.21@4220.33,3736 ccw(c4210.31,3725.98) 4210.31,3740.16 ccw(c4210.31,3754.34) J28.21@4220.33,3744.31 ; v1@6958.47,3040.09 ccw(c6942.26,3056.31) 6965.19,3056.31 ccw(c6988.13,3056.31) v1@6971.91,3040.09 ; v1@6961.3,3037.26 ccw(c6951.91,3046.65) 6965.19,3046.65 ccw(c6978.47,3046.65) v1@6969.08,3037.26 ; v1(6965.19,3033.37) 6965.19,3095.19 6988.82,3118.82 U34.12@7038.5,3118.82 U34.12@7040.19,3118.82 ; U34.12@7009.2,3115.99 ccw(c7002.37,3109.16) 7002.37,3118.82 ccw(c7002.37,3128.48) U34.12@7009.2,3121.65
  MidLayer1 w4: v1@4570.52,3611.21 cw(c4570.52,3588.27) 4586.74,3604.49 cw(c4602.96,3620.71) v1@4580.02,3620.71 ; v1@4570.52,3615.21 cw(c4570.52,3601.93) 4579.91,3611.32 cw(c4589.3,3620.71) v1@4576.02,3620.71 ; v1(4570.52,3620.71) 4615.19,3576.04 4615.19,3508.37 4631.86,3491.71 4656.86,3491.71 4723.52,3425.04 4723.52,3375.04 4731.19,3367.37 4731.19,3271.37 4698.52,3238.71 4698.52,3156.04 v1(4686.19,3143.71)
  MidLayer2 w4: v1(4198.52,3758.37) 4265.19,3758.37 4415.19,3608.37 4440.19,3608.37 4452.52,3620.71 v1(4570.52,3620.71) ; v1@4202.41,3754.49 cw(c4211.8,3745.1) 4211.8,3758.37 cw(c4211.8,3771.65) v1@4202.41,3762.26 ; v1@4205.24,3751.66 cw(c4221.46,3735.44) 4221.46,3758.37 cw(c4221.46,3781.31) v1@4205.24,3765.09 ; v1@4563.81,3613.99 ccw(c4547.59,3597.77) 4547.59,3620.71 ccw(c4547.59,3643.64) v1@4563.81,3627.43 ; v1@4566.64,3616.82 ccw(c4557.25,3607.43) 4557.25,3620.71 ccw(c4557.25,3633.99) v1@4566.64,3624.6
  Bottom Layer w4: v1@4570.52,3611.21 cw(c4570.52,3588.27) 4586.74,3604.49 cw(c4602.96,3620.71) v1@4580.02,3620.71 ; v1@4570.52,3615.21 cw(c4570.52,3601.93) 4579.91,3611.32 cw(c4589.3,3620.71) v1@4576.02,3620.71 ; v1(4570.52,3620.71) 4616.19,3575.04 4681.86,3575.04 4691.19,3565.71 4741.19,3565.71 4848.52,3458.37 4848.52,3350.04 4865.19,3333.37 4991.63,3333.37 5035,3290 5077.19,3290 5151.15,3216.04 5283.56,3216.04 5300.9,3233.37 5436.56,3233.37 5452.56,3249.37 5521.19,3249.37 5528.86,3241.71 5556.86,3241.71 5620.21,3178.35 5620.21,3163 5634.17,3149.04 5798.52,3149.04 5873.52,3224.04 5873.52,3291.71 6023.52,3441.71 6198.52,3441.71 6199.52,3442.71 6222.52,3442.71 6238.52,3426.71 6238.52,3423.37 6223.52,3408.37 6223.52,3375.04 6248.52,3350.04 6480.59,3350.04 6502.26,3328.37 6670,3328.37 6803.52,3328.37 6856.86,3275.04 6931.86,3275.04 6965.19,3241.71 v1(6965.19,3033.37) ; R187.2@4656.18,3141.88 4679.69,3141.87 4686.19,3135.37 v1(4686.19,3143.71) ; R187.2@4658.83,3141.87 ccw(c4658.83,3171.07) v1@4679.47,3150.43 ; R187.2@4659.94,3138.11 cw(c4669.02,3129.03) 4669.02,3141.87 cw(c4669.02,3154.72) R187.2@4659.94,3145.64 ; R187.2@4662.77,3135.29 cw(c4678.68,3119.38) 4678.68,3141.87 cw(c4678.68,3164.37) R187.2@4662.77,3148.46 ; 4667.68,3141.87 cw(c4667.68,3125.2) v1@4679.47,3136.99 ; 4668.49,3141.87 ccw(c4668.49,3161.41) v1@4682.3,3147.6 ; v1@6958.47,3040.09 ccw(c6942.26,3056.31) 6965.19,3056.31 ccw(c6988.13,3056.31) v1@6971.91,3040.09 ; v1@6961.3,3037.26 ccw(c6951.91,3046.65) 6965.19,3046.65 ccw(c6978.47,3046.65) v1@6969.08,3037.26
LEDS#.LED5.RED: J28.23 R185.2 U34.8 | length 5491.7
  Top Layer w4: v1@4198.27,3700.79 J28.23@4246.61,3700.79 J28.23@4248.52,3700.79 ; v1@4201.41,3696.15 cw(c4212.6,3684.96) 4212.6,3700.79 ; v1@4204.24,3693.32 cw(c4222.26,3675.3) J28.23@4222.26,3700.79 ; v1@4204.24,3706.76 ccw(c4218.66,3721.17) J28.23@4218.66,3700.79 ; J28.23@4220.33,3696.63 ccw(c4210.31,3686.61) 4210.31,3700.79 ccw(c4210.31,3714.97) J28.23@4220.33,3704.94 ; v1@4668.02,3175.04 cw(c4645.09,3175.04) 4661.31,3158.82 cw(c4677.52,3142.61) v1@4677.52,3165.54 ; v1@4672.02,3175.04 cw(c4658.75,3175.04) 4668.14,3165.65 cw(c4677.52,3156.26) v1@4677.52,3169.54 ; v1(4677.52,3175.04) 4631.52,3129.04 4631.52,3009.79 4648.19,2993.12 4648.19,2900.37 4706.86,2841.71 v1@4780.19,2841.71 ; 4754.9,2841.71 cw(c4754.9,2813.08) v1@4775.14,2833.32 ; 4762.95,2841.71 ccw(c4762.95,2858.95) v1@4775.14,2846.76 ; 4764.55,2841.71 cw(c4764.55,2822.74) v1@4777.97,2836.15 ; U34.8@7035.68,3013.63 cw(c7028.85,3006.8) 7038.5,3006.8 cw(c7048.16,3006.8) U34.8@7041.33,3013.63 ; U34.8@7038.5,3016.46 7038.5,2881.5 7110,2810 7110,2726.87 7068,2684.87 7068,2618.23 v1(7104.86,2581.37) ; v1@7095.36,2581.37 ccw(c7072.42,2581.37) 7088.64,2597.59 ccw(c7104.86,2613.81) v1@7104.86,2590.87 ; v1@7099.36,2581.37 ccw(c7086.08,2581.37) 7095.47,2590.76 ccw(c7104.86,2600.15) v1@7104.86,2586.87
  MidLayer2 w4: v1(4115.19,3641.71) 4173.52,3700.04 v1(4197.52,3700.04) ; v1@4115.19,3647.21 ccw(c4115.19,3660.49) 4124.58,3651.1 ccw(c4133.97,3641.71) v1@4120.69,3641.71 ; v1@4115.19,3651.21 ccw(c4115.19,3674.14) 4131.41,3657.93 ccw(c4147.63,3641.71) v1@4124.69,3641.71 ; v1@4190.81,3693.32 ccw(c4174.59,3677.11) 4174.59,3700.04 ccw(c4174.59,3722.98) v1@4190.81,3706.76 ; v1@4193.64,3696.15 ccw(c4184.25,3686.76) 4184.25,3700.04 ccw(c4184.25,3713.32) v1@4193.64,3703.93 ; v1@4529.19,3182.21 cw(c4529.19,3159.27) 4545.41,3175.49 cw(c4561.63,3191.71) v1@4538.69,3191.71 ; v1@4529.19,3186.21 cw(c4529.19,3172.93) 4538.58,3182.32 cw(c4547.97,3191.71) v1@4534.69,3191.71 ; v1(4529.19,3191.71) 4565.9,3155 4657.48,3155 v1(4677.52,3175.04) ; v1@4668.02,3175.04 cw(c4645.09,3175.04) 4661.31,3158.82 cw(c4677.52,3142.61) v1@4677.52,3165.54 ; v1@4672.02,3175.04 cw(c4658.75,3175.04) 4668.14,3165.65 cw(c4677.52,3156.26) v1@4677.52,3169.54
  Bottom Layer w4: v1@4108.47,3634.99 cw(c4092.26,3618.77) 4115.19,3618.77 cw(c4138.13,3618.77) v1@4121.91,3634.99 ; v1@4111.3,3637.82 cw(c4101.91,3628.43) 4115.19,3628.43 cw(c4128.47,3628.43) v1@4119.08,3637.82 ; v1(4115.19,3641.71) 4115.19,3586.37 4140.19,3561.37 4140.19,3491.71 4148.52,3483.37 4148.52,3203.02 4188.5,3163.04 4441.88,3163.04 4466.21,3187.37 4490,3187.37 4494.33,3191.71 v1(4529.19,3191.71) ; v1@4522.47,3184.99 ccw(c4506.26,3168.77) 4506.26,3191.71 ccw(c4506.26,3214.64) v1@4522.47,3198.43 ; v1@4525.3,3187.82 ccw(c4515.91,3178.43) 4515.91,3191.71 ccw(c4515.91,3204.99) v1@4525.3,3195.6 ; R185.2@4656.28,3196.94 cw(c4657.48,3181.46) 4668.46,3192.44 ; R185.2@4656.59,3192.95 cw(c4658.36,3170.05) 4674.6,3186.29 ; R185.2@4665.19,3195.71 4677.52,3183.37 v1(4677.52,3175.04) ; R185.2@4665.5,3198.26 ccw(c4672.4,3198.26) 4667.52,3193.38 ; R185.2@4666.39,3194.5 cw(c4651.73,3179.84) v1@4672.12,3176.05 ; 4671.76,3189.13 cw(c4660.79,3178.16) v1@4676.05,3175.32 ; v1(4781.86,2840.04) 5099.52,2840.04 5114.52,2825.04 5219.52,2825.04 5386.19,2658.37 5440.19,2658.37 5465.19,2683.37 5573.52,2683.37 5581.86,2691.71 5614.19,2691.71 5623.52,2682.37 5623.52,2670.04 5709.86,2583.71 5773.56,2583.71 5803.9,2553.37 6200.54,2553.37 6246.88,2507.04 6555.52,2507.04 6598.52,2550.04 6925.86,2550.04 6975.86,2600.04 7086.19,2600.04 v1(7104.86,2581.37) ; v1@4785.75,2836.15 cw(c4795.14,2826.76) 4795.14,2840.04 cw(c4795.14,2853.32) v1@4785.75,2843.93 ; v1@4788.57,2833.32 cw(c4804.79,2817.11) 4804.79,2840.04 cw(c4804.79,2862.98) v1@4788.57,2846.76 ; v1@7095.36,2581.37 ccw(c7072.42,2581.37) 7088.64,2597.59 ccw(c7104.86,2613.81) v1@7104.86,2590.87 ; v1@7099.36,2581.37 ccw(c7086.08,2581.37) 7095.47,2590.76 ccw(c7104.86,2600.15) v1@7104.86,2586.87
LEDS#.LED6.BLUE: J28.32 R189.2 U35.4 | length 4776.5
  Top Layer w4: J28.32@4323.39,3523.62 4358.19,3523.62 ; J28.32@4349.99,3519.82 cw(c4358.19,3512.88) 4358.19,3523.62 ; J28.32@4349.99,3527.42 ccw(c4358.19,3534.37) 4358.19,3523.62 ; v1@4471.02,3458.37 ccw(c4448.09,3458.37) 4464.31,3474.59 ccw(c4480.52,3490.81) v1@4480.52,3467.87 ; v1@4475.02,3458.37 ccw(c4461.75,3458.37) 4471.14,3467.76 ccw(c4480.52,3477.15) v1@4480.52,3463.87 ; v1(4480.52,3458.37) 4455.52,3483.37 4402.52,3483.37 4398.52,3487.37 4398.52,3516.71 4381.86,3533.37 4367.94,3533.37 4358.19,3523.62 ; v1@4643.14,3233.43 ccw(c4626.92,3249.64) 4649.86,3249.64 ccw(c4672.79,3249.64) 4656.57,3233.43 ccw(c4672.79,3249.64) 4672.79,3226.71 ccw(c4672.79,3203.77) v1@4656.57,3219.99 ; v1@4645.97,3230.6 ccw(c4636.58,3239.99) 4649.86,3239.99 ccw(c4663.14,3239.99) 4653.75,3230.6 ccw(c4663.14,3239.99) 4663.14,3226.71 ccw(c4663.14,3213.43) v1@4653.75,3222.82 ; v1@4676.36,3357.37 cw(c4653.42,3357.37) 4669.64,3341.16 cw(c4685.86,3324.94) v1@4685.86,3347.87 ; v1@4680.36,3357.37 cw(c4667.08,3357.37) 4676.47,3347.99 cw(c4685.86,3338.6) v1@4685.86,3351.87 ; v1(4685.86,3357.37) 4649.86,3321.37 v1(4649.86,3226.71) 4693.29,3226.71 4706.86,3213.14 4706.86,3017.71 v1(4740.19,2984.37) ; v1@4730.69,2984.37 ccw(c4707.76,2984.37) 4723.97,3000.59 ccw(c4740.19,3016.81) v1@4740.19,2993.87 ; v1@4734.69,2984.37 ccw(c4721.41,2984.37) 4730.8,2993.76 ccw(c4740.19,3003.15) v1@4740.19,2989.87 ; U35.4@7130,3093.23 7175.04,3093.23 v1(7190.19,3108.37) ; U35.4@7159.31,3090.4 cw(c7166.14,3083.57) 7166.14,3093.23 cw(c7166.14,3102.88) U35.4@7159.31,3096.06
  MidLayer2 w4: v1(5364.86,2975.04) 5395.73,2975.04 5402.69,2982 5533,2982 5624.52,2890.48 5624.52,2863.37 5638.52,2849.37 5811.88,2849.37 5843.88,2817.37 6039.52,2817.37 6074.19,2782.71 6140.52,2782.71 v1(6142.86,2780.37) ; v1@5368.75,2971.15 cw(c5378.14,2961.76) 5378.14,2975.04 cw(c5378.14,2988.32) v1@5368.75,2978.93 ; v1@5371.57,2968.32 cw(c5387.79,2952.11) 5387.79,2975.04 cw(c5387.79,2997.98) v1@5371.57,2981.76 ; 6114.29,2782.71 cw(c6114.29,2751.81) v1@6136.14,2773.66 ; 6123.95,2782.71 cw(c6123.95,2761.46) v1@6138.97,2776.49 ; 6125.55,2782.71 ccw(c6125.55,2797.68) v1@6136.14,2787.09
  Bottom Layer w4: v1(4480.52,3458.37) 4526.19,3458.37 4556.86,3427.71 4556.86,3412.71 4569.52,3400.04 4665.19,3400.04 4685.86,3379.37 ; v1@4484.41,3454.49 cw(c4493.8,3445.1) 4493.8,3458.37 cw(c4493.8,3471.65) v1@4484.41,3462.26 ; v1@4487.24,3451.66 cw(c4503.46,3435.44) 4503.46,3458.37 cw(c4503.46,3481.31) v1@4487.24,3465.09 ; v1@4644.74,3234.71 ccw(c4631.35,3255.62) 4656.18,3255.62 4656.18,3228.72 4658.19,3226.71 v1(4649.86,3226.71) ; v1@4646.89,3231.34 ccw(c4636.03,3248.31) R189.2@4656.18,3248.31 ; v1@4649.05,3227.97 ccw(c4640.71,3241) 4656.18,3241 ; R189.2@4649.59,3248.54 cw(c4633.68,3232.63) 4656.18,3232.63 cw(c4678.68,3232.64) R189.2@4662.77,3248.54 ; R189.2@4652.42,3251.37 cw(c4643.34,3242.29) 4656.18,3242.29 cw(c4669.02,3242.29) R189.2@4659.94,3251.37 ; v1@4679.34,3364.29 ccw(c4665.14,3379.37) 4685.86,3379.37 ; v1@4682.09,3361.38 ccw(c4673.86,3370.11) 4685.86,3370.11 ccw(c4697.85,3370.11) v1@4689.63,3361.38 ; v1(4685.86,3357.37) 4685.86,3379.37 ; v1@4692.37,3364.29 cw(c4706.58,3379.37) 4685.86,3379.37 ; v1@4738.42,2982.61 ccw(c4756.69,3000.87) 4756.69,2975.04 ; v1(4740.19,2984.37) 4749.52,2975.04 4920.48,2975.04 4995.48,3050.04 5065.19,3050.04 5131.86,2983.37 5151.88,2963.35 5164.86,2950.37 5217.56,2950.37 5226,2958.81 5254,2958.81 5271.11,2941.71 5315.19,2941.71 5348.52,2975.04 ; v1@4741.25,2985.44 ccw(c4766.35,3010.53) 4766.35,2975.04 ; v1@4744.08,2988.26 ccw(c4776,3020.19) 4776,2975.04 ; v1@4746.91,2991.09 ccw(c4785.66,3029.84) 4785.66,2975.04 ; v1@5356.6,2970.34 ccw(c5348.52,2965.75) 5348.52,2975.04 ; v1@5356.6,2979.74 cw(c5348.52,2984.33) 5348.52,2975.04 ; v1(5364.86,2975.04) 5348.52,2975.04 ; v1(6142.86,2780.37) 6190.52,2828.04 6309.21,2828.04 6331.88,2805.37 6406.86,2805.37 6443.19,2841.71 6601.51,2841.71 6627.17,2816.04 6828.21,2816.04 7120.54,3108.37 v1(7190.19,3108.37) ; v1@6142.86,2785.87 ccw(c6142.86,2799.15) 6152.25,2789.76 ccw(c6161.64,2780.37) v1@6148.36,2780.37 ; v1@6142.86,2789.87 ccw(c6142.86,2812.81) 6159.07,2796.59 ccw(c6175.29,2780.37) v1@6152.36,2780.37 ; v1@7183.47,3101.66 ccw(c7167.26,3085.44) 7167.26,3108.37 ccw(c7167.26,3131.31) v1@7183.47,3115.09 ; v1@7186.3,3104.49 ccw(c7176.91,3095.1) 7176.91,3108.37 ccw(c7176.91,3121.65) v1@7186.3,3112.26
LEDS#.LED6.GREEN: J28.35 R190.2 U35.6 | length 4311.7
  Top Layer w4: v1@4191.02,3411.37 ccw(c4168.09,3411.37) 4184.31,3427.59 ccw(c4200.52,3443.81) v1@4200.52,3420.87 ; v1@4195.02,3411.37 ccw(c4181.75,3411.37) 4191.13,3420.76 ccw(c4200.52,3430.15) v1@4200.52,3416.87 ; v1(4200.52,3411.37) 4181.86,3430.04 4181.86,3447.9 4198.52,3464.57 J28.35@4246.61,3464.57 ; J28.35@4220.33,3460.41 ccw(c4210.31,3450.39) 4210.31,3464.57 ccw(c4210.31,3478.75) J28.35@4220.33,3468.72 ; U35.6@7130,3042.05 7190,3042.05 7198.52,3033.52 v1(7198.52,2982.37) ; U35.6@7159.31,3039.22 cw(c7166.14,3032.39) 7166.14,3042.05 cw(c7166.14,3051.71) U35.6@7159.31,3044.88 ; v1@7191.81,2989.09 ccw(c7175.59,3005.31) 7198.52,3005.31 ccw(c7221.46,3005.31) v1@7205.24,2989.09 ; v1@7194.64,2986.26 ccw(c7185.25,2995.65) 7198.52,2995.65 ccw(c7211.8,2995.65) v1@7202.41,2986.26
  Bottom Layer w4: v1@4200.52,3401.87 cw(c4200.52,3378.94) 4216.74,3395.16 cw(c4232.96,3411.37) v1@4210.02,3411.37 ; v1@4200.52,3405.87 cw(c4200.52,3392.6) 4209.91,3401.99 cw(c4219.3,3411.37) v1@4206.02,3411.37 ; v1(4200.52,3411.37) 4261.86,3350.04 4396.86,3350.04 4398.52,3351.71 4398.52,3384.37 4405.86,3391.71 4438.86,3391.71 4488.86,3341.71 4626.97,3341.71 R190.2@4656.18,3312.5 4686.05,3312.5 4693.66,3304.89 4731.86,3266.71 4731.86,3225.04 4748.52,3208.37 4761.52,3208.37 4766.19,3203.71 4766.19,3174.04 4806.86,3133.37 4815.86,3124.37 5041.9,3124.37 5059.56,3142.04 5121.82,3142.04 5154.48,3109.37 5316.56,3109.37 5367.56,3058.37 5611.63,3058.37 5623.86,3046.14 5623.86,2928.52 5643.37,2909 5750.27,2909 5785,2874.27 5785,2824.81 5765.19,2805 5765.19,2789.55 5775.44,2779.3 5789.94,2779.3 5802.66,2792.02 5839.87,2792.02 5842.52,2789.37 5890.19,2741.71 5973.52,2741.71 5990.19,2758.37 6065.19,2758.37 6090.19,2733.37 6274.86,2733.37 6293.52,2752.04 6407.52,2752.04 6438.86,2783.37 6674.19,2783.37 6682.52,2791.71 6837.82,2791.71 6912.82,2866.71 7074.52,2866.71 7198.52,2990.71 v1(7198.52,2982.37) ; 4639.43,3329.25 ccw(c4656.18,3346) R190.2@4656.18,3322.31 ; 4640.62,3328.06 cw(c4625.55,3312.99) R190.2@4646.86,3312.99 ; R190.2@4646.26,3322.42 ccw(c4656.18,3332.34) R190.2@4656.18,3318.31 ; R190.2@4647.45,3321.23 cw(c4639.21,3312.99) R190.2@4650.86,3312.99 ; R190.2@4659.94,3308.74 cw(c4669.02,3299.66) 4669.02,3312.5 cw(c4669.02,3325.34) R190.2@4659.94,3316.26 ; R190.2@4662.77,3305.91 cw(c4678.68,3290) 4678.68,3312.5 cw(c4678.68,3335) R190.2@4662.77,3319.09 ; 7168.08,2960.26 cw(c7198.52,2929.82) v1@7198.52,2972.87 ; 7174.91,2967.09 cw(c7198.52,2943.48) v1@7198.52,2976.87 ; 7181.74,2973.92 cw(c7198.52,2957.14) v1@7198.52,2980.87
LEDS#.LED6.RED: J28.28 R188.2 U35.2 | length 11542.7
  Top Layer w4: J28.28@4323.39,3602.36 4331.86,3602.36 4331.86,3608.37 4341.52,3608.37 4349.86,3600.04 4414.86,3600.04 4423.52,3591.37 4423.52,3541.37 4473.19,3491.71 4498.52,3491.71 4506.86,3483.37 4506.86,3399.04 v1(4518.86,3387.04) ; J28.28@4346.84,3603.69 ccw(c4355.64,3612.49) 4355.64,3600.04 ; J28.28@4349.67,3598.21 cw(c4354.09,3593.79) 4354.09,3600.04 ; J28.28@4349.67,3606.52 ccw(c4365.3,3622.15) 4365.3,3600.04 ; 7089.68,3134.68 cw(c7103.52,3120.83) U35.2@7103.52,3140.41 ; 7090,3115.19 7090,3135 7099.41,3144.41 U35.2@7130,3144.41 U35.2@7131.86,3144.41 ; 7090.19,3115 7090.19,2925.04 7156.86,2858.37 7156.86,2658.37 7173.52,2641.71 7331.86,2641.71 7348.52,2625.04 7348.52,2491.37 v1(7373.19,2466.71) ; 7096.5,3141.5 cw(c7103.52,3134.49) U35.2@7103.52,3144.41 ; v1@7363.69,2466.71 ccw(c7340.76,2466.71) 7356.97,2482.93 ccw(c7373.19,2499.14) v1@7373.19,2476.21 ; v1@7367.69,2466.71 ccw(c7354.41,2466.71) 7363.8,2476.1 ccw(c7373.19,2485.49) v1@7373.19,2472.21 ; v1(7411.52,2491.71) 7427.19,2491.71 7431.86,2487.04 7431.86,2450.04 7465.19,2416.71 7465.19,2366.71 7481.86,2350.04 7548.52,2350.04 7557.5,2341.06 7557.5,2322.75 ; 7556.86,2322.11 7556.86,2150.04 7590.19,2116.71 7590.19,2012.39 7567.5,1989.7 7567.5,1962.75 7622.75,1907.5 7655,1907.5 7664.5,1917 7745.85,1917 ; v1(7631.86,258.37) 7655,281.52 7655,1250 7840.19,1435.19 7840.19,1891.71 7814.4,1917.5 7745.85,1917.5 ; v1@7631.86,263.87 ccw(c7631.86,277.15) 7641.25,267.76 ccw(c7650.64,258.37) v1@7637.36,258.37 ; v1@7631.86,267.87 ccw(c7631.86,290.81) 7648.07,274.59 ccw(c7664.29,258.37) v1@7641.36,258.37
  MidLayer1 w4: v1@4748.69,3233.37 cw(c4725.76,3233.37) 4741.97,3217.16 cw(c4758.19,3200.94) v1@4758.19,3223.87 ; v1@4752.69,3233.37 cw(c4739.41,3233.37) 4748.8,3223.99 cw(c4758.19,3214.6) v1@4758.19,3227.87 ; v1(4758.19,3233.37) 4723.52,3198.71 4723.52,3175.04 4740.19,3158.37 4798.52,3158.37 4807.52,3149.37 4807.52,2775.71 4656.86,2625.04 4656.86,1915 4606.52,1864.67 4606.52,1038.48 4619.96,1025.04 4690,1025.04 4700,1035.04 4700,1064.2 4797.8,1162 4872.27,1162 5032.19,1002.08 5032.19,294.12 5176.31,150 5645,150 5730,235 6263.69,235 6393.69,105 7478.48,105 v1(7631.86,258.37) ; v1@7622.36,258.37 cw(c7599.42,258.37) 7615.64,242.16 cw(c7631.86,225.94) v1@7631.86,248.87 ; v1@7626.36,258.37 cw(c7613.08,258.37) 7622.47,248.99 cw(c7631.86,239.6) v1@7631.86,252.87
  Bottom Layer w4: v1(4518.86,3387.04) 4523.52,3391.71 4633.85,3391.71 R188.2@4656.18,3369.38 ; v1@4519.92,3385.98 cw(c4533.75,3372.15) 4533.75,3391.71 ; v1@4522.75,3383.15 cw(c4543.4,3362.5) 4543.4,3391.71 ; v1@4525.57,3380.32 cw(c4553.06,3352.84) 4553.06,3391.71 ; v1@4525.57,3393.76 ccw(c4530.53,3398.71) 4530.53,3391.71 ; 4639.43,3386.12 ccw(c4656.18,3402.87) R188.2@4656.18,3379.19 ; 4640.62,3384.94 cw(c4625.55,3369.87) R188.2@4646.86,3369.87 ; R188.2@4646.26,3379.29 ccw(c4656.18,3389.21) R188.2@4656.18,3375.19 ; R188.2@4647.45,3378.11 cw(c4639.21,3369.87) R188.2@4650.86,3369.87 ; R188.2@4656.86,3358.37 4675.52,3339.71 4715.19,3339.71 4731.19,3323.71 4731.19,3281.71 4758.19,3254.71 ; R188.2@4657.45,3368.51 ccw(c4671.35,3364.39) 4661.1,3354.13 ; R188.2@4661.28,3367.37 ccw(c4678.69,3362.22) 4665.85,3349.38 ; R188.2@4665.12,3366.24 ccw(c4686.03,3360.05) 4670.61,3344.62 ; v1@4751.83,3240.44 ccw(c4738.99,3254.71) 4758.19,3254.71 ; v1@4754.51,3237.46 ccw(c4747.07,3245.72) 4758.19,3245.72 ccw(c4769.31,3245.72) v1@4761.87,3237.46 ; v1(4758.19,3233.37) 4758.19,3254.71 ; v1@4764.55,3240.44 cw(c4777.39,3254.71) 4758.19,3254.71 ; v1@7373.1,2460.21 ccw(c7373.33,2476.37) 7384.76,2464.94 ; v1@7373.15,2464.21 ccw(c7373.52,2489.56) 7391.45,2471.63 ; v1(7373.19,2466.71) 7386.52,2466.71 v1(7411.52,2491.71) cw(c7374.09,2529.14) v1@7373.33,2476.21 ; v1@7373.21,2468.21 ccw(c7373.71,2502.75) 7398.14,2478.32 ; v1@7373.27,2472.21 ccw(c7373.9,2515.95) v1@7404.83,2485.01 ; v1@7402.02,2491.71 cw(c7379.09,2491.71) 7395.31,2475.49 cw(c7411.52,2459.27) v1@7411.52,2482.21 ; v1@7406.02,2491.71 cw(c7392.75,2491.71) 7402.14,2482.32 cw(c7411.52,2472.93) v1@7411.52,2486.21
LEDS#.LED7.BLUE: J28.36 R192.2 U35.10 | length 7745.2
  Top Layer w4: J28.36@4323.39,3444.88 4337.7,3444.88 4367.86,3475.04 4415.19,3475.04 4431.86,3458.37 v1(4431.86,3455.04) ; J28.36@4343.39,3444.88 cw(c4357.12,3444.88) 4347.41,3454.59 ; J28.36@4347.39,3444.88 cw(c4370.77,3444.88) 4354.24,3461.42 ; J28.36@4351.39,3444.88 cw(c4384.43,3444.88) 4361.06,3468.25 ; 4420.27,3469.96 cw(c4405.58,3455.27) v1@4426.36,3455.09 ; 4421.33,3468.9 ccw(c4431.86,3479.43) v1@4431.86,3464.54 ; v1@4576.86,3446.87 cw(c4576.86,3423.94) 4593.07,3440.16 cw(c4609.29,3456.37) v1@4586.36,3456.37 ; v1@4576.86,3450.87 cw(c4576.86,3437.6) 4586.25,3446.99 cw(c4595.64,3456.37) v1@4582.36,3456.37 ; v1(4576.86,3456.37) 4606.86,3426.37 4606.86,3175.04 4594.07,3162.26 4560.3,3162.26 4531.52,3133.48 4531.52,2686.69 4698.52,2519.69 v4(4698.52,1955) ; v1(6756.86,1399.04) 6791.19,1433.37 6948.52,1433.37 6976.9,1405 7101.9,1405 7131.86,1375.04 7323.52,1375.04 7340.19,1358.37 7340.19,1299.81 ; v1@6756.86,1404.54 ccw(c6756.86,1417.82) 6766.25,1408.43 ccw(c6775.64,1399.04) v1@6762.36,1399.04 ; v1@6756.86,1408.54 ccw(c6756.86,1431.48) 6773.07,1415.26 ccw(c6789.29,1399.04) v1@6766.36,1399.04 ; 7340,1300 7340.19,1299.81 ; U35.10@7348.5,3066.71 7373.52,3066.71 7390.19,3050.04 7390.19,2941.71 7323.52,2875.04 7323.52,2675.04 7356.86,2641.71 7356.86,2508.37 7448.52,2416.71 7448.52,1328.33 7456.86,1320 7456.86,1295 7446.86,1285 7355,1285 7340.19,1299.81 ; U35.10@7378.98,3067.64 ccw(c7394.41,3067.64) 7383.5,3056.73
  MidLayer1 w4: v1(4431.86,3455.04) v1(4493.52,3516.71) ; v1@4431.86,3460.54 ccw(c4431.86,3473.82) 4441.25,3464.43 ccw(c4450.64,3455.04) v1@4437.36,3455.04 ; v1@4431.86,3464.54 ccw(c4431.86,3487.48) 4448.07,3471.26 ccw(c4464.29,3455.04) v1@4441.36,3455.04 ; v1@4484.02,3516.71 cw(c4461.09,3516.71) 4477.31,3500.49 cw(c4493.52,3484.27) v1@4493.52,3507.21 ; v1@4488.02,3516.71 cw(c4474.75,3516.71) 4484.14,3507.32 cw(c4493.52,3497.93) v1@4493.52,3511.21
  MidLayer2 w4: v4(4698.52,1955) 4732.86,1955 5013.15,1674.71 5404.82,1674.71 5562.82,1516.71 6143.17,1516.71 6284.84,1375.04 6485,1375.04 6509,1399.04 v1(6756.86,1399.04) ; v4@4702.63,1950.89 cw(c4712.55,1940.97) 4712.55,1955 cw(c4712.55,1969.03) v4@4702.63,1959.11 ; v4@4705.46,1948.06 cw(c4722.21,1931.31) 4722.21,1955 cw(c4722.21,1978.69) v4@4705.46,1961.94 ; v1@6750.14,1392.32 ccw(c6733.92,1376.11) 6733.92,1399.04 ccw(c6733.92,1421.98) v1@6750.14,1405.76 ; v1@6752.97,1395.15 ccw(c6743.58,1385.76) 6743.58,1399.04 ccw(c6743.58,1412.32) v1@6752.97,1402.93
  Bottom Layer w4: v1(4493.52,3516.71) 4516.52,3516.71 v1(4576.86,3456.37) 4579.86,3456.37 4581.86,3458.37 4630.86,3458.37 4655.86,3433.37 4656.18,3433.37 R192.2@4656.18,3426.25 ; v1@4497.41,3512.82 cw(c4506.8,3503.43) 4506.8,3516.71 cw(c4506.8,3529.99) v1@4497.41,3520.6 ; v1@4500.24,3509.99 cw(c4516.46,3493.77) 4516.46,3516.71 cw(c4516.46,3539.64) v1@4500.24,3523.43 ; v1@4567.36,3456.37 ccw(c4544.42,3456.37) 4560.64,3472.59 ccw(c4576.86,3488.81) v1@4576.86,3465.87 ; v1@4571.36,3456.37 ccw(c4558.08,3456.37) 4567.47,3465.76 ccw(c4576.86,3475.15) v1@4576.86,3461.87 ; v1@4580.75,3452.49 cw(c4594.96,3438.27) 4594.96,3458.37 cw(c4594.96,3474.48) v1@4583.57,3463.09 ; v1@4583.57,3449.66 cw(c4604.62,3428.61) 4604.62,3458.37 ; 4635.81,3453.42 cw(c4609.13,3426.74) R192.2@4646.86,3426.74 ; 4642.64,3446.59 cw(c4622.79,3426.74) R192.2@4650.86,3426.74 ; 4649.47,3439.76 cw(c4636.45,3426.74) R192.2@4654.86,3426.74 ; 4651.04,3438.19 ccw(c4656.18,3443.33) R192.2@4656.18,3436.06 ; R192.2@4656.18,3426.25 4656.18,3425.76 R192.2@4656.18,3426.25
